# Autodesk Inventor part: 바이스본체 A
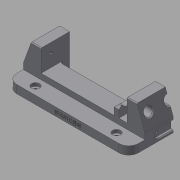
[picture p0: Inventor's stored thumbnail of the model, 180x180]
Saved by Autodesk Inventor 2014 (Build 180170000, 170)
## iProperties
Created: 2017-04
Part Number: 바이스본체 A
Material: 일반
Document SubType Name: Modeling
Designer: mduedu
Density: 1 g/cm^3
Appearance: 기본값
Mass: 119.631 g
Surface Area: 276.734 cm^2
Volume: 119.631 cm^3
Author: mduedu
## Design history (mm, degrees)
sketch "스케치1"
  geometry: L1 (-75, 0)-(75, 0); L2 (-75, 0)-(-75, 17); L3 (-53, 17)-(53, 17); L4 (75, 17)-(75, 0); L5 (-75, 17)-(-65.173, 44); L6 (-65.173, 44)-(-53, 44); L7 (-53, 44)-(-53, 17); L8 (0, 0)-(0, 17); L9 (75, 17)-(65.173, 44); L10 (65.173, 44)-(53, 44); L11 (53, 44)-(53, 17); 1 further point
  constraints: 22 end point, 4 perpendicular, 2 horizontal alignment, 2 midpoint, 2 symmetric about line, 1 coincident, 1 collinear, 1 horizontal, 1 vertical
  dimensions: "d0" = 150 distance of L1.start L1.end; "d1" = 17 distance of L1.start L2.end; "d2" = 27 distance of L3.start L6.end; "d3" = 22 distance of L3.start L2.end; "d4" = 70 deg angle of L3 L5; "d54" = 20 deg angle of L9 L4
extrude "돌출1" new body sketch "스케치1" stored distance "d5" = 70; taper "d6" = 0 deg
sketch "스케치2"
  geometry: L1 (0, 70)-(106, 70) reference; L2 (106, 70)-(106, 0) reference; L3 (106, 0)-(0, 0) reference; L4 (0, 47)-(106, 47); L5 (106, 47)-(106, 23); L6 (106, 23)-(0, 23); L7 (0, 23)-(0, 47); L8 (0, 70)-(0, 0) reference; 2 further points
  constraints: 8 end point, 2 parallel, 2 point on line, 1 horizontal, 1 horizontal alignment, 1 midpoint, 1 perpendicular
  dimensions: "d7" = 24 distance between parallel lines of L6 L4
extrude "돌출2" cut sketch "스케치2" stored distance "d9" = 70; taper "d10" = 0 deg
sketch "스케치3"
  geometry: L1 (22, -23)-(128, -23) reference; L2 (128, -47)-(22, -47) reference; L3 (22, -18)-(128, -18); L4 (128, -52)-(22, -52); L5 (22, -18)-(22, -52); L6 (128, -18)-(128, -52); 1 further point
  constraints: 8 end point, 3 parallel, 2 point on line, 1 perpendicular
  dimensions: "d11" = 5 distance between parallel lines of L3 L1; "d12" = 5 distance between parallel lines of L4 L2
extrude "돌출3" cut sketch "스케치3" distance "d13" = 12; taper "d14" = 0 deg
fillet "모깎기1" dims "d15" = 3, "d16" = 3
sketch "스케치4"
  geometry: L1 (103, 23)-(3, 23) reference; L2 (0, 26)-(0, 0) reference; L3 (106, 0)-(0, 0) reference; L4 (106, 26)-(106, 0) reference; L5 (96, 0)-(90, 0); L6 (90, 0)-(90, 19.5); L7 (96, 19.5)-(96, 0); L8 (90, 19.5)-(96, 19.5); A1 r 3 centre (3, 26) between (0, 26) and (3, 23) reference; A2 r 3 centre (103, 26) between (103, 23) and (106, 26) reference; 1 further point
  constraints: 8 end point, 2 perpendicular, 1 horizontal, 1 parallel, 1 point on line
  dimensions: "d17" = 10 distance between parallel lines of L7 L4; "d18" = 6 distance between parallel lines of L7 L6; "d27" = 3.5 distance between parallel lines of L8 L1
extrude "돌출4" join sketch "스케치4" distance "d19" = 12; taper "d20" = 0 deg
chamfer "모따기1" distance "d21" = 3; stored, may be unused: second distance "d22" = 2, angle "d23" = 45 deg
chamfer "모따기2" distance "d24" = 3; stored, may be unused: second distance "d25" = 2, angle "d26" = 45 deg
sketch "스케치5"
  geometry: L1 (-15.5, 35.8)-(-15.5, -25.8) reference; L2 (19.5, 0)-(0, 0) reference; C1 r 6.5 at (9.5, 15); 1 further point
  constraints: 1 centre point
  dimensions: "d28" = 13 diameter of C1; "d30" = 15 distance from line of C1.centre L2; "d31" = 25 distance from line of C1.centre L1
extrude "돌출5" cut sketch "스케치5" stored distance "d32" = 12; taper "d33" = 0 deg
sketch "스케치6"
  geometry: C1 r 5 at (-10, 15); C2 r 5 at (-60, 15); A1 r 6.5 centre (-10, 15) between (-15.766, 12) and (-4.234, 12) reference; A2 r 6.5 centre (-60, 15) between (-65.766, 12) and (-54.234, 12) reference; 1 further point
  constraints: 2 centre point, 2 coincident
  dimensions: "d34" = 10 diameter of C1; "d35" = 10 diameter of C2 (= d34)
extrude "돌출6" cut sketch "스케치6" stored distance "d36" = 12; taper "d37" = 0 deg
chamfer "모따기3" distance "d38" = 1; stored, may be unused: second distance "d39" = 2, angle "d40" = 45 deg
chamfer "모따기4" distance "d41" = 1; stored, may be unused: second distance "d42" = 2, angle "d43" = 45 deg
sketch "스케치7"
  geometry: L1 (-35, 35.8)-(-35, -25.8) reference; L2 (-70, 0)-(0, 0) reference; C1 r 5 at (-35, 15); 1 further point
  constraints: 1 centre point, 1 point on line
  dimensions: "d44" = 10 diameter of C1; "d45" = 15 distance from line of C1.centre L2
extrude "돌출7" cut sketch "스케치7" stored distance "d46" = 12; taper "d47" = 0 deg
chamfer "모따기5" distance "d48" = 1; stored, may be unused: second distance "d49" = 2, angle "d50" = 45 deg
node "작업축1"
sketch "스케치8"
  geometry: L1 (-105, 32)-(105, 32) reference; L2 (58, 32)-(64, 32); L3 (64, 32)-(64, 40); L4 (64, 40)-(58, 40); L5 (58, 40)-(58, 32); L6 (53, 38)-(53, 26) reference; 1 further point
  constraints: 8 end point, 2 parallel, 1 horizontal, 1 perpendicular, 1 point on line
  dimensions: "d51" = 5 distance from line of L6 L2.start; "d52" = 6 distance of L3.end L4.end; "d53" = 16 diameter of L4 L1
revolve "회전1" sketch "스케치8" stored, may be unused: angle "d55" = 90 deg
fillet "모깎기2"
chamfer "모따기6" distance "d56" = 1; stored, may be unused: second distance "d57" = 2, angle "d58" = 45 deg
sketch "스케치9"
  geometry: L1 (17.5, 3)-(52.5, 3); L2 (52.5, 13)-(17.5, 13); L3 (70, 0)-(0, 0) reference; L4 (17.5, 8)-(52.5, 8); A1 r 5 centre (17.5, 8) between (17.5, 13) and (17.5, 3); A2 r 5 centre (52.5, 8) between (52.5, 3) and (52.5, 13); 3 further points
  constraints: 6 end point, 4 point on circle, 3 tangent, 2 centre point, 2 midpoint, 2 parallel, 1 horizontal, 1 vertical alignment
  dimensions: "d59" = 35 distance of L4.start L4.end; "d61" = 5 radius of A2; "d62" = 8 distance between parallel lines of L3 L4
extrude "돌출8" cut sketch "스케치9" distance "d63" = 3; taper "d64" = 0 deg
chamfer "모따기7" distance "d65" = 1; stored, may be unused: second distance "d66" = 2, angle "d67" = 45 deg
chamfer "모따기8" distance "d68" = 1; stored, may be unused: second distance "d69" = 2, angle "d70" = 45 deg
feature "분할1"
sketch "스케치10"
  geometry: L1 (35, 27)-(0, 27) reference; L2 (0, 0)-(0, 27) reference; 1 further point
  dimensions: "d85" = 11.5 distance from line of point (12, 15.5) L1; "d86" = 12 distance from line of point (12, 15.5) L2
hole "구멍1" sketch "스케치10" at (12, 15.5) diameter "d71" = 3.242; stored, may be unused: countersink angle "d75" = 90 deg, drill point angle "d77" = 120 deg; dims "d72" = 6, "d73" = 4, "d74" = 2, "d76" = 8
sketch "스케치11"
  geometry: A1 r 5 centre (17.5, 8) between (17.5, 13) and (17.5, 3) reference; 1 further point
  constraints: 1 coincident
hole "구멍3" sketch "스케치11" at (17.5, 8) diameter "d78" = 2.459; stored, may be unused: countersink angle "d82" = 90 deg, drill point angle "d84" = 120 deg; dims "d79" = 4.5, "d80" = 4, "d81" = 2, "d83" = 6
sketch "스케치13"
  geometry: L1 (75, 0)-(75, 35) reference; L2 (-75, 0)-(-75, 35) reference; L3 (-75, 35)-(75, 35); L4 (75, 35)-(75, 55); L5 (75, 55)-(-75, 55); L6 (-75, 55)-(-75, 35); 1 further point
  constraints: 8 end point, 2 parallel, 1 horizontal, 1 perpendicular, 1 point on line
  dimensions: "d90" = 20 distance between parallel lines of L5 L3; "d94" = 150 distance of L4.end L5.end (derived)
extrude "돌출9" join sketch "스케치13" distance "d92" = 10; taper "d93" = 0 deg
sketch "스케치14"
  geometry: L1 (-75, -35)-(-75, -55) reference; L2 (75, -55)-(75, -35) reference; L3 (-75, -45)-(75, -45); 3 further points
  constraints: 2 end point, 2 midpoint, 2 point on line
  dimensions: "d95" = 50 horizontal distance of point (-50, -45) point (0, 0); "d96" = 100 distance of point (50, -45) point (-50, -45)
fillet "모깎기3" dims "d97" = 12
chamfer "모따기9" distance "d98" = 1; stored, may be unused: second distance "d99" = 2, angle "d100" = 45 deg
hole "구멍4" sketch "스케치14" diameter "d101" = 4.134; stored, may be unused: countersink angle "d105" = 90 deg, drill point angle "d107" = 118 deg; dims "d102" = 6, "d103" = 10, "d104" = 4, "d106" = 8
sketch "스케치15"
  geometry: L1 (0, 0)-(126, 0) reference; 3 further points
  constraints: 1 midpoint, 1 vertical alignment, 1 other
  dimensions: "d109" = 5 distance from line of point (63, 5) L1
feature "엠보싱2" sketch "스케치15" dims "d0" = 150, "d1" = 17, "d2" = 27, "d3" = 22, "d4" = 70 deg, "d54" = 20 deg, "d110" = 0.5, "d111" = 0
node "솔리드1"
mirror "대칭1"
mirror "대칭2"
mirror "대칭3"
mirror "대칭4"
node "투영된 루프1"
